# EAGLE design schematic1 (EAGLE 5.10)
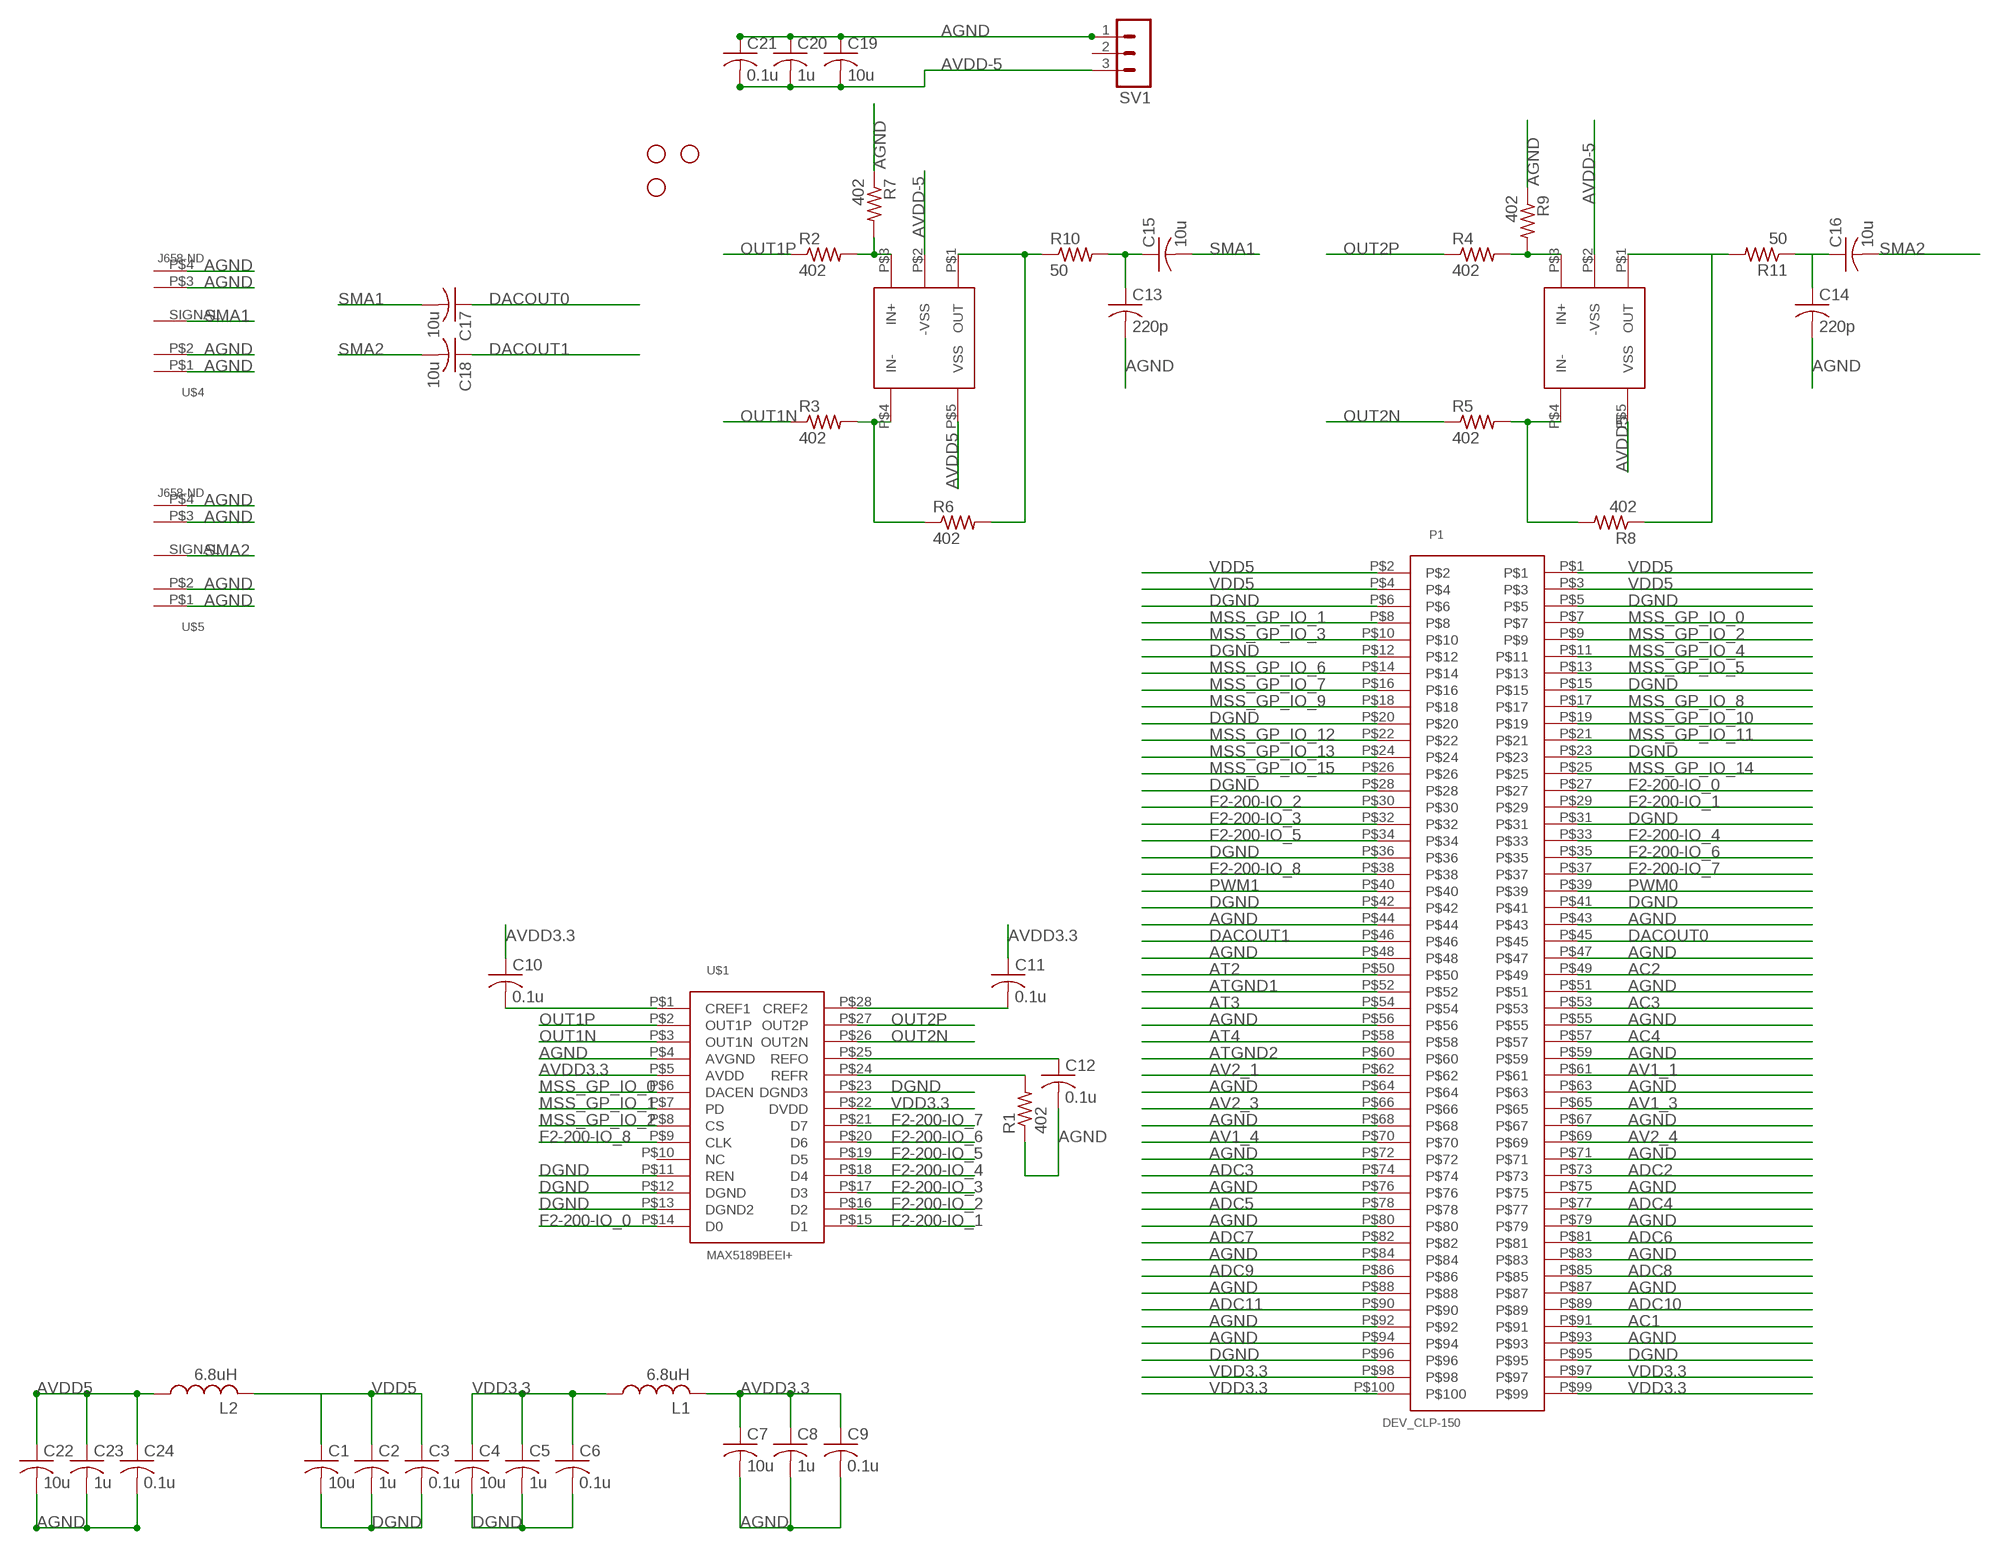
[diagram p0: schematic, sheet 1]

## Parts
C1  10u  C-USC0603  [C0603]
C2  1u  C-USC0603  [C0603]
C3  0.1u  C-USC0603  [C0603]
C4  10u  C-USC0603  [C0603]
C5  1u  C-USC0603  [C0603]
C6  0.1u  C-USC0603  [C0603]
C7  10u  C-USC0603  [C0603]
C8  1u  C-USC0603  [C0603]
C9  0.1u  C-USC0603  [C0603]
C10  0.1u  C-USC0603  [C0603]
C11  0.1u  C-USC0603  [C0603]
C12  0.1u  C-USC0603  [C0603]
C13  220p  C-USC0603  [C0603]
C14  220p  C-USC0603  [C0603]
C15  10u  C-USC0603  [C0603]
C16  10u  C-USC0603  [C0603]
C17  10u  C-USC0603  [C0603]
C18  10u  C-USC0603  [C0603]
C19  10u  C-USC0603  [C0603]
C20  1u  C-USC0603  [C0603]
C21  0.1u  C-USC0603  [C0603]
C22  10u  C-USC0603  [C0603]
C23  1u  C-USC0603  [C0603]
C24  0.1u  C-USC0603  [C0603]
JP1  STAND-OFF  [STAND-OFF]
JP2  STAND-OFF  [STAND-OFF]
JP3  STAND-OFF  [STAND-OFF]
L1  6.8uH  L-US  [L1210]
L2  6.8uH  L-US  [L1210]
P1  DEV_CLP-150  [CLP-150]
R1  402  R-US_R0603  [R0603]
R2  402  R-US_R0603  [R0603]
R3  402  R-US_R0603  [R0603]
R4  402  R-US_R0603  [R0603]
R5  402  R-US_R0603  [R0603]
R6  402  R-US_R0603  [R0603]
R7  402  R-US_R0603  [R0603]
R8  402  R-US_R0603  [R0603]
R9  402  R-US_R0603  [R0603]
R10  50  R-US_R0603  [R0603]
R11  50  R-US_R0603  [R0603]
SV1  MA03-1  [MA03-1]
U$1  MAX5189BEEI+  [QSOP]
U$3  MAX4104EUK+T  [SOT-5]
U$4  J658-ND  [SMA-SMD]
U$5  J658-ND  [SMA-SMD]
U$8  MAX4104EUK+T  [SOT-5]

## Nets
AC1: P1.P$91
AC2: P1.P$49
AC3: P1.P$53
AC4: P1.P$57
ADC2: P1.P$73
ADC3: P1.P$74
ADC4: P1.P$77
ADC5: P1.P$78
ADC6: P1.P$81
ADC7: P1.P$82
ADC8: P1.P$85
ADC9: P1.P$86
ADC10: P1.P$89
ADC11: P1.P$90
AGND: C7.2 C8.2 C9.2 C12.2 C13.2 C14.2 C19.1 C20.1 C21.1 C22.2 C23.2 C24.2 P1.P$43 P1.P$44 P1.P$47 P1.P$48 P1.P$51 P1.P$55 P1.P$56 P1.P$59 P1.P$63 P1.P$64 P1.P$67 P1.P$68 P1.P$71 P1.P$72 P1.P$75 P1.P$76 P1.P$79 P1.P$80 P1.P$83 P1.P$84 P1.P$87 P1.P$88 P1.P$92 P1.P$93 P1.P$94 R1.1 R7.1 R9.1 SV1.1 U$1.P$4(AVGND) U$4.P$1(GND1) U$4.P$2(GND2) U$4.P$3(GND3) U$4.P$4(GND4) U$5.P$1(GND1) U$5.P$2(GND2) U$5.P$3(GND3) U$5.P$4(GND4)
AT2: P1.P$50
AT3: P1.P$54
AT4: P1.P$58
ATGND1: P1.P$52
ATGND2: P1.P$60
AV1_1: P1.P$61
AV1_3: P1.P$65
AV1_4: P1.P$70
AV2_1: P1.P$62
AV2_3: P1.P$66
AV2_4: P1.P$69
AVDD3.3: C7.1 C8.1 C9.1 C10.1 C11.1 L1.2 U$1.P$5(AVDD)
AVDD5: C22.1 C23.1 C24.1 L2.1 U$3.P$5(VSS) U$8.P$5(VSS)
AVDD-5: C19.2 C20.2 C21.2 SV1.3 U$3.P$2(-VSS) U$8.P$2(-VSS)
DACOUT0: C17.1 P1.P$45
DACOUT1: C18.1 P1.P$46
DGND: C1.2 C2.2 C3.2 C4.2 C5.2 C6.2 P1.P$5 P1.P$6 P1.P$12 P1.P$15 P1.P$20 P1.P$23 P1.P$28 P1.P$31 P1.P$36 P1.P$41 P1.P$42 P1.P$95 P1.P$96 U$1.P$11(REN) U$1.P$12(DGND) U$1.P$13(DGND2) U$1.P$23(DGND3)
F2-200-IO_0: P1.P$27 U$1.P$14(D0)
F2-200-IO_1: P1.P$29 U$1.P$15(D1)
F2-200-IO_2: P1.P$30 U$1.P$16(D2)
F2-200-IO_3: P1.P$32 U$1.P$17(D3)
F2-200-IO_4: P1.P$33 U$1.P$18(D4)
F2-200-IO_5: P1.P$34 U$1.P$19(D5)
F2-200-IO_6: P1.P$35 U$1.P$20(D6)
F2-200-IO_7: P1.P$37 U$1.P$21(D7)
F2-200-IO_8: P1.P$38 U$1.P$9(CLK)
MSS_GP_IO_0: P1.P$7 U$1.P$6(DACEN)
MSS_GP_IO_1: P1.P$8 U$1.P$7(PD)
MSS_GP_IO_2: P1.P$9 U$1.P$8(CS)
MSS_GP_IO_3: P1.P$10
MSS_GP_IO_4: P1.P$11
MSS_GP_IO_5: P1.P$13
MSS_GP_IO_6: P1.P$14
MSS_GP_IO_7: P1.P$16
MSS_GP_IO_8: P1.P$17
MSS_GP_IO_9: P1.P$18
MSS_GP_IO_10: P1.P$19
MSS_GP_IO_11: P1.P$21
MSS_GP_IO_12: P1.P$22
MSS_GP_IO_13: P1.P$24
MSS_GP_IO_14: P1.P$25
MSS_GP_IO_15: P1.P$26
N$1: R5.2 R8.2 U$8.P$4(IN-)
N$2: R4.2 R9.2 U$8.P$3(IN+)
N$3: R6.2 R10.1 U$3.P$1(OUT)
N$4: R3.2 R6.1 U$3.P$4(IN-)
N$5: C10.2 U$1.P$1(CREF1)
N$6: C13.1 C15.1 R10.2
N$7: R2.2 R7.2 U$3.P$3(IN+)
N$8: R8.1 R11.2 U$8.P$1(OUT)
N$9: C14.1 C16.1 R11.1
N$23: R1.2 U$1.P$24(REFR)
N$24: C12.1 U$1.P$25(REFO)
N$27: C11.2 U$1.P$28(CREF2)
OUT1N: R3.1 U$1.P$3(OUT1N)
OUT1P: R2.1 U$1.P$2(OUT1P)
OUT2N: R5.1 U$1.P$26(OUT2N)
OUT2P: R4.1 U$1.P$27(OUT2P)
PWM0: P1.P$39
PWM1: P1.P$40
SMA1: C15.2 C17.2 U$4.SIGNAL
SMA2: C16.2 C18.2 U$5.SIGNAL
VDD3.3: C4.1 C5.1 C6.1 L1.1 P1.P$97 P1.P$98 P1.P$99 P1.P$100 U$1.P$22(DVDD)
VDD5: C1.1 C2.1 C3.1 L2.2 P1.P$1 P1.P$2 P1.P$3 P1.P$4
Unconnected: SV1.2 U$1.P$10(NC)

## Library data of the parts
C1-C24 = rcl:C-US: CAPACITOR, American symbol
JP1-JP3 = SparkFun:STAND-OFF: Stand Off
L1 L2 = sam:L-US: INDUCTOR, American symbol
P1 = EECS370:DEV_CLP-150
R1-R11 = rcl:R-US_: RESISTOR, American symbol
SV1 = con-lstb:MA03-1: PIN HEADER; OC_FARNELL: unknown; OC_NEWARK: unknown
U$1 = sam:MAX5189BEEI+
U$3 U$8 = sam:MAX4104EUK+T
U$4 U$5 = sam:J658-ND

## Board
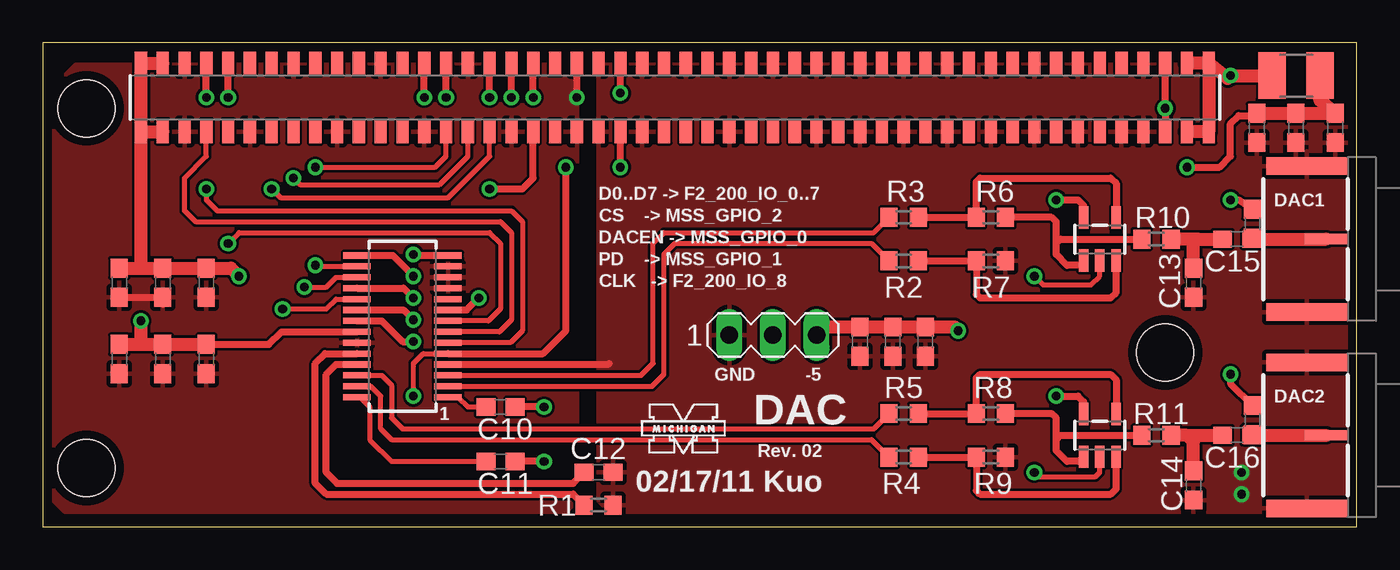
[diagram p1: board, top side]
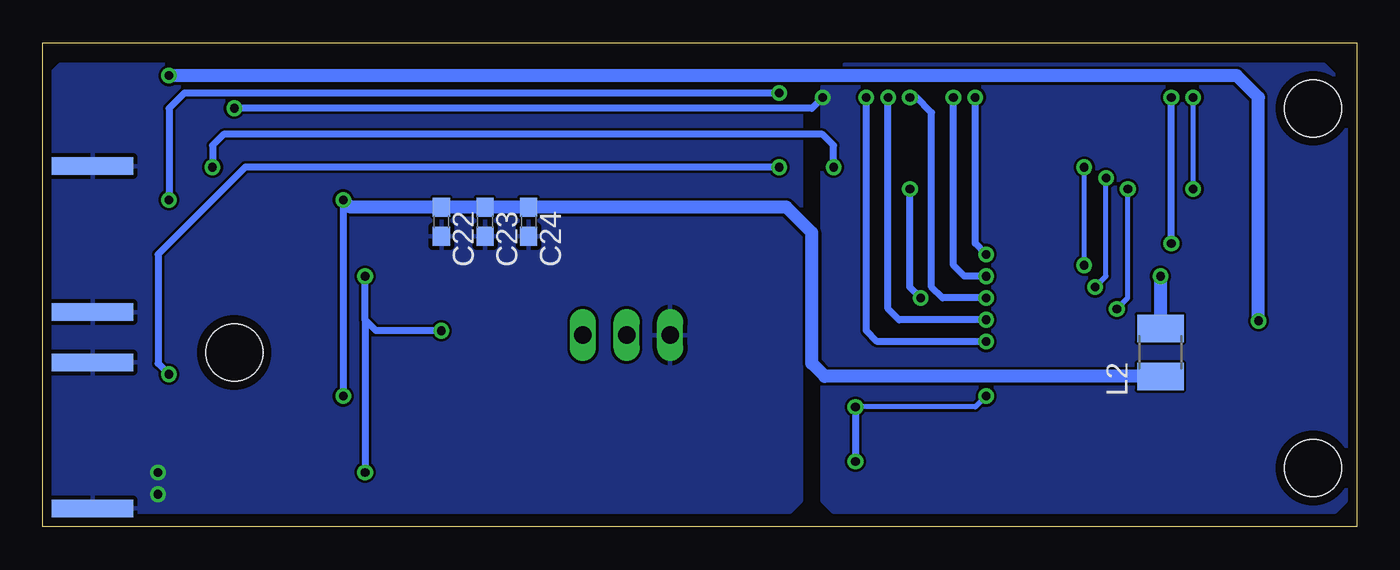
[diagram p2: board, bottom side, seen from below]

Size 76.56 x 28.19 mm. Coordinates in mm from the lower left corner, seen from the top.
Outline: 0,0 76.56,0 76.56,28.19 0,28.19 0,0
Copper layers (1*16): Top 0.0178mm / dielectric 1.4986mm / Bottom 0.0178mm
Design rules "SSC-EAGLE-2Lyr_v1.0.0.3": minimum track width 6mil, minimum drill 14mil, track to track 6mil, track to pad 6mil, pad to pad 6mil, via to via 6mil, smd to smd 6mil, copper to edge 20mil, drill to drill 16mil, minimum pad ring 8mil, minimum via ring 8mil, stop-mask expansion 3mil, vias tented up to drill 0mil, thermal gap 10mil

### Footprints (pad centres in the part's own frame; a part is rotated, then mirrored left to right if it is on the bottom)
C0603 = smd 1.1 x 1: 1 -0.85,0; 2 0.85,0
STAND-OFF = hole 3.302: 0,0
L1210 = smd 1.6 x 2.7: 1 -1.4,0; 2 1.4,0
CLP-150 = smd 0.711 x 1.35: P$1 -31.115,1.99; P$2 -31.115,-1.99; P$3 -29.845,1.99; P$4 -29.845,-1.99; P$5 -28.575,1.99; P$6 -28.575,-1.99; P$7 -27.305,1.99; P$8 -27.305,-1.99; P$9 -26.035,1.99; P$10 -26.035,-1.99; P$11 -24.765,1.99; P$12 -24.765,-1.99; P$13 -23.495,1.99; P$14 -23.495,-1.99; P$15 -22.225,1.99; P$16 -22.225,-1.99; P$17 -20.955,1.99; P$18 -20.955,-1.99; P$19 -19.685,1.99; P$20 -19.685,-1.99; P$21 -18.415,1.99; P$22 -18.415,-1.99; P$23 -17.145,1.99; P$24 -17.145,-1.99; P$25 -15.875,1.99; P$26 -15.875,-1.99; P$27 -14.605,1.99; P$28 -14.605,-1.99; P$29 -13.335,1.99; P$30 -13.335,-1.99; P$31 -12.065,1.99; P$32 -12.065,-1.99; P$33 -10.795,1.99; P$34 -10.795,-1.99; P$35 -9.525,1.99; P$36 -9.525,-1.99; P$37 -8.255,1.99; P$38 -8.255,-1.99; P$39 -6.985,1.99; P$40 -6.985,-1.99; P$41 -5.715,1.99; P$42 -5.715,-1.99; P$43 -4.445,1.99; P$44 -4.445,-1.99; P$45 -3.175,1.99; P$46 -3.175,-1.99; P$47 -1.905,1.99; P$48 -1.905,-1.99; P$49 -0.635,1.99; P$50 -0.635,-1.99; P$51 0.635,1.99; P$52 0.635,-1.99; P$53 1.905,1.99; P$54 1.905,-1.99; P$55 3.175,1.99; P$56 3.175,-1.99; P$57 4.445,1.99; P$58 4.445,-1.99; P$59 5.715,1.99; P$60 5.715,-1.99; P$61 6.985,1.99; P$62 6.985,-1.99; P$63 8.255,1.99; P$64 8.255,-1.99; P$65 9.525,1.99; P$66 9.525,-1.99; P$67 10.795,1.99; P$68 10.795,-1.99; P$69 12.065,1.99; P$70 12.065,-1.99; P$71 13.335,1.99; P$72 13.335,-1.99; P$73 14.605,1.99; P$74 14.605,-1.99; P$75 15.875,1.99; P$76 15.875,-1.99; P$77 17.145,1.99; P$78 17.145,-1.99; P$79 18.415,1.99; P$80 18.415,-1.99; P$81 19.685,1.99; P$82 19.685,-1.99; P$83 20.955,1.99; P$84 20.955,-1.99; P$85 22.225,1.99; P$86 22.225,-1.99; P$87 23.495,1.99; P$88 23.495,-1.99; P$89 24.765,1.99; P$90 24.765,-1.99; P$91 26.035,1.99; P$92 26.035,-1.99; P$93 27.305,1.99; P$94 27.305,-1.99; P$95 28.575,1.99; P$96 28.575,-1.99; P$97 29.845,1.99; P$98 29.845,-1.99; P$99 31.115,1.99; P$100 31.115,-1.99
R0603 = smd 1 x 1.1: 1 -0.85,0; 2 0.85,0
MA03-1 = drill 1.016 long: 1 -2.54,0; 2 0,0; 3 2.54,0
QSOP = smd 1.6 x 0.356: P$1 -2.655,4.128; P$2 -2.655,3.493; P$3 -2.655,2.857; P$4 -2.655,2.223; P$5 -2.655,1.587; P$6 -2.655,0.953; P$7 -2.655,0.318; P$8 -2.655,-0.318; P$9 -2.655,-0.953; P$10 -2.655,-1.587; P$11 -2.655,-2.223; P$12 -2.655,-2.857; P$13 -2.655,-3.493; P$14 -2.655,-4.128; P$15 2.655,-4.128; P$16 2.655,-3.493; P$17 2.655,-2.857; P$18 2.655,-2.223; P$19 2.655,-1.587; P$20 2.655,-0.953; P$21 2.655,-0.318; P$22 2.655,0.318; P$23 2.655,0.953; P$24 2.655,1.587; P$25 2.655,2.223; P$26 2.655,2.857; P$27 2.655,3.493; P$28 2.655,4.128
SOT-5 = smd 1.3 x 0.55: P$1 -1.25,0.95; P$2 -1.25,0; P$3 -1.25,-0.95; P$4 1.25,-0.95; P$5 1.25,0.95
SMA-SMD = smd 1.02 x 4.75: P$1 -4.25,0; P$2 4.25,0 | smd 1.02 x 4.75 bottom: P$3 4.25,0; P$4 -4.25,0 | smd 0.6 x 2.5: SIGNAL 0,1.125

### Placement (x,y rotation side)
C1  4.45,14.22 270 top
C2  9.53,14.22 270 top
C3  6.99,14.22 270 top
C4  6.99,9.78 270 top
C5  9.53,9.78 270 top
C6  4.45,9.78 270 top
C7  75.31,23.24 270 top
C8  73.03,23.24 270 top
C9  70.74,23.24 270 top
C10  26.67,6.99 180 top
C11  26.67,3.81 180 top
C12  32.38,3.17 0 top
C13  67.06,14.22 270 top
C14  67.06,2.41 270 top
C15  69.6,16.76 0 top
C16  69.6,5.33 0 top
C17  70.48,17.65 270 top
C18  70.48,6.22 270 top
C19  47.62,10.79 90 top
C20  49.53,10.79 90 top
C21  51.44,10.79 90 top
C22  53.34,17.78 270 bottom
C23  50.8,17.78 270 bottom
C24  48.26,17.78 270 bottom
JP1  2.54,3.43 0 top
JP2  2.54,24.38 0 top
JP3  65.41,10.16 0 top
L1  73.03,26.29 0 top
L2  11.43,10.16 90 bottom
P1  36.83,25.02 0 top
R1  32.38,1.27 180 top
R2  50.16,15.49 0 top
R3  50.16,18.03 0 top
R4  50.16,4.06 0 top
R5  50.16,6.6 0 top
R6  55.24,18.03 0 top
R7  55.24,15.49 180 top
R8  55.24,6.6 180 top
R9  55.24,4.06 180 top
R10  64.9,16.76 0 top
R11  64.9,5.33 180 top
SV1  42.55,11.18 0 top
U$1  20.95,11.68 180 top
U$3  61.59,16.76 90 top
U$4  73.66,16.76 270 top
U$5  73.66,5.33 270 top
U$6  [UMICH]  34.8,4.06 0 top
U$8  61.59,5.33 90 top

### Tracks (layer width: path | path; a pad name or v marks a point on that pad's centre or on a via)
AGND  (via drill 0.51)
  Top 0.406: U$1.P$4 32.96,9.46 33.02,9.53
  other vias: 69.85,3.17 69.85,1.91
  pour Top: 76.2,26.29 76.2,1.52 75.56,0.89 33.02,0.89 32.38,1.52 32.38,26.92 75.56,26.92
  pour Bottom: 76.2,26.29 75.56,26.92 32.38,26.92 32.38,1.52 33.02,0.89 75.56,0.89 76.2,1.52
AVDD3.3  (via drill 0.51)
  Top 0.305: U$1.P$5 22.16,10.1 21.59,9.53 v21.59,7.62
  Top 0.406: v66.67,20.95 68.58,20.95 69.22,21.59 69.22,23.5 69.68,23.96 70.61,23.96 C9.1 | v29.21,3.81 C11.1 | v29.21,6.99 C10.1 | v30.48,20.95 30.48,11.43 29.15,10.1 U$1.P$5
  Top 0.762: L1.2 74.42,24.85 C7.1 C8.1 C9.1
  Bottom 0.305: v21.59,7.62 22.23,6.99 v29.21,6.99
  Bottom 0.406: v66.67,20.95 66.67,22.23 66.04,22.86 31.11,22.86 30.48,22.23 v30.48,20.95 | v29.21,6.99 v29.21,3.81
AVDD5  (via drill 0.51)
  Top 0.406: U$8.P$5 60.65,7.3 60.33,7.62 v59.05,7.62 | U$3.P$5 60.65,18.73 60.33,19.05 v59.05,19.05
  Bottom 0.406: v59.05,19.05 v59.05,7.62
  Bottom 0.762: L2.1 30.98,8.76 31.75,9.53 31.75,17.14 33.23,18.63 C24.1 C23.1 C22.1 58.63,18.63 v59.05,19.05
AVDD-5  (via drill 0.51)
  Top 0.305: U$8.P$2 61.59,3.17 61.34,2.92 58.04,2.92 v57.78,3.17 | U$3.P$2 61.59,14.61 61.09,14.1 58.29,14.1 v57.78,14.61
  Top 0.762: SV1.3 45.55,11.64 C19.2 C20.2 C21.2 53.12,11.64 v53.34,11.43
  Bottom 0.406: 57.78,12.06 v57.78,14.61 | v53.34,11.43 57.15,11.43 57.78,12.06 | 57.78,12.06 v57.78,3.17
DACOUT0  (via drill 0.51)
  Top 0.406: v33.66,25.27 P1.P$45 | v69.22,19.05 69.68,19.05 C17.1
  Bottom 0.406: v33.66,25.27 68.33,25.27 69.22,24.38 v69.22,19.05
DACOUT1  (via drill 0.51)
  Top 0.406: v33.66,20.95 P1.P$46 | v69.22,8.89 69.22,8.34 C18.1
  Bottom 0.406: v33.66,20.95 64.77,20.95 69.85,15.88 69.85,9.53 v69.22,8.89
DGND  (via drill 0.51)
  Top 0.406: C1.2 C3.2 6.99,12.95 | v31.11,25.02 P1.P$41 | P1.P$96 v65.41,24.38 P1.P$95
  Bottom 0.406: v65.41,24.38 31.75,24.38 v31.11,25.02
  pour Top: 0.64,25.65 0.64,1.52 1.27,0.89 30.48,0.89 31.11,1.52 31.11,25.65 29.84,26.92 1.91,26.92
  pour Bottom: 0.64,25.65 0.64,1.52 1.27,0.89 30.48,0.89 31.11,1.52 31.11,25.65 29.84,26.92 1.91,26.92
F2-200-IO_0  (via drill 0.51)
  Top 0.406: v22.23,25.02 P1.P$27 | U$1.P$14 21.65,15.81 v21.59,15.88
  Bottom 0.406: v22.23,25.02 22.23,16.51 v21.59,15.88
F2-200-IO_1  (via drill 0.51)
  Top 0.406: v23.5,25.02 P1.P$29 | U$1.P$15 20.38,15.81 v21.59,14.61
  Bottom 0.406: v23.5,25.02 23.5,15.24 22.86,14.61 v21.59,14.61
F2-200-IO_2  (via drill 0.51)
  Top 0.305: P1.P$30 23.5,21.59 22.86,20.95 v15.88,20.95 | U$1.P$16 15.94,15.18 v15.88,15.24
  Bottom 0.305: v15.88,15.24 v15.88,20.95
F2-200-IO_3  (via drill 0.51)
  Top 0.305: P1.P$32 24.77,21.59 23.11,19.94 14.99,19.94 v14.61,20.32 | U$1.P$17 17.08,14.54 16.51,13.97 v15.24,13.97
  Bottom 0.305: v14.61,20.32 14.61,14.61 v15.24,13.97
F2-200-IO_4  (via drill 0.51)
  Top 0.406: v26.04,25.02 P1.P$33 | U$1.P$18 21.02,13.91 v21.59,13.34
  Bottom 0.406: v21.59,13.34 24.13,13.34 24.77,13.97 24.77,24.13 25.65,25.02 v26.04,25.02
F2-200-IO_5  (via drill 0.51)
  Top 0.305: P1.P$34 26.04,21.59 23.62,19.18 13.84,19.18 v13.34,19.68 | U$1.P$19 17.08,13.27 16.51,12.7 v13.97,12.7
  Bottom 0.305: v13.34,19.68 13.34,13.34 v13.97,12.7
F2-200-IO_6  (via drill 0.51)
  Top 0.406: v27.3,25.02 P1.P$35 | U$1.P$20 21.02,12.64 v21.59,12.06
  Bottom 0.406: v27.3,25.02 27.3,12.7 26.67,12.06 v21.59,12.06
F2-200-IO_7  (via drill 0.51)
  Top 0.406: v28.57,25.02 P1.P$37 | U$1.P$21 19.75,12 20.95,10.79 v21.59,10.79
  Bottom 0.406: v28.57,25.02 28.57,11.43 27.94,10.79 v21.59,10.79
F2-200-IO_8  (via drill 0.51)
  Top 0.406: U$1.P$9 24.7,12.64 v25.4,13.34 | v26.04,19.68 27.94,19.68 28.57,20.32 P1.P$38
  Bottom 0.406: v25.4,13.34 26.04,13.97 v26.04,19.68
MSS_GP_IO_0  (via drill 0.51)
  Top 0.305: U$1.P$6 27.24,10.73 27.94,11.43 27.94,17.78 27.3,18.41 10.16,18.41 9.53,19.05 v9.53,19.68
  Top 0.406: v9.53,25.02 P1.P$7
  Bottom 0.305: v9.53,19.68 v9.53,25.02
MSS_GP_IO_1
  Top 0.305: U$1.P$7 26.61,11.37 27.3,12.06 27.3,17.14 26.67,17.78 8.89,17.78 8.26,18.41 8.26,20.32 9.53,21.59 P1.P$8
MSS_GP_IO_2  (via drill 0.51)
  Top 0.305: U$1.P$8 25.97,12 26.67,12.7 26.67,16.51 26.04,17.14 11.43,17.14 v10.79,16.51
  Top 0.406: v10.79,25.02 P1.P$9
  Bottom 0.406: v10.79,16.51 v10.79,25.02
N$1
  Top 0.406: R5.2 R8.2 54.4,8.68 54.61,8.89 62.23,8.89 62.55,8.57 U$8.P$4
N$2
  Top 0.406: R4.2 R9.2 54.4,2.12 54.61,1.91 62.23,1.91 62.55,2.22 U$8.P$3
N$3
  Top 0.406: 59.05,16.51 59.05,15.88 59.69,15.24 60.62,15.24 U$3.P$1 | R10.1 59.31,16.76 59.05,16.51 | R6.2 58.8,18.03 59.05,17.78 59.05,16.51
N$4
  Top 0.406: U$3.P$4 62.55,20 62.23,20.32 54.61,20.32 54.4,20.11 R6.1 R3.2
N$5
  Top 0.305: U$1.P$1 24.19,7.56 24.77,6.99 C10.2
N$6
  Top 0.762: 67.31,16.76 R10.2 | 67.31,16.76 C15.1 | C13.1 67.06,16.51 67.31,16.76
N$7
  Top 0.406: R2.2 R7.2 54.4,13.55 54.61,13.34 62.23,13.34 62.55,13.65 U$3.P$3
N$8
  Top 0.406: R8.1 58.8,6.6 59.05,6.35 59.05,5.08 | 59.05,5.08 59.05,4.45 59.69,3.81 60.37,3.81 U$8.P$1 | R11.2 59.31,5.33 59.05,5.08
N$9
  Top 0.762: 66.67,5.33 R11.1 | 66.67,5.33 C16.1 | C14.1 67.06,4.95 66.67,5.33
N$23
  Top 0.406: U$1.P$24 16.45,10.1 15.88,9.53 15.88,2.54 16.51,1.91 30.9,1.91 R1.2
N$24
  Top 0.406: U$1.P$25 17.08,9.46 16.51,8.89 16.51,3.17 17.14,2.54 30.9,2.54 C12.1
N$27
  Top 0.305: U$1.P$28 18.48,7.56 19.05,6.99 19.05,5.08 20.32,3.81 C11.2
OUT1N
  Top 0.305: U$1.P$3 34.86,8.83 35.56,9.53 35.56,16.51 36.2,17.14 48.43,17.14 R3.1
OUT1P
  Top 0.305: U$1.P$2 35.5,8.19 36.2,8.89 36.2,15.88 36.83,16.51 48.3,16.51 R2.1
OUT2N
  Top 0.305: U$1.P$26 19.75,8.83 20.32,8.26 20.32,6.35 20.95,5.71 48.43,5.71 R5.1
OUT2P
  Top 0.305: U$1.P$27 19.11,8.19 19.68,7.62 19.68,5.71 20.32,5.08 48.3,5.08 R4.1
SMA1
  Top 0.762: C15.2 C17.2 70.52,16.76 U$4.SIGNAL
SMA2
  Top 0.762: U$5.SIGNAL 70.52,5.33 C18.2 C16.2
VDD3.3  (via drill 0.51)
  Top 0.406: U$1.P$22 13.91,11.37 13.17,10.63 C5.1
  Top 0.762: P1.P$99 P1.P$100 P1.P$98 | P1.P$99 P1.P$97 | P1.P$99 69.05,26.12 v69.22,26.29 L1.1 | C6.1 5.71,10.63 | 5.71,10.63 C4.1 C5.1 | 5.71,10.63 v5.71,12
  Bottom 0.762: v69.22,26.29 6.99,26.29 5.71,25.02 v5.71,12
VDD5  (via drill 0.51)
  Top 0.762: P1.P$2 P1.P$4 | C1.1 5.71,15.07 | 5.71,15.07 C3.1 C2.1 10.96,15.07 v11.43,14.61 | P1.P$2 P1.P$1 P1.P$3 | 5.71,15.07 P1.P$2
  Bottom 0.762: v11.43,14.61 L2.2

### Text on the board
tPlace: D0..D7 -> F2_200_IO_0..7 | DAC1 | CS -> MSS_GPIO_2 | DACEN -> MSS_GPIO_0 | PD -> MSS_GPIO_1 | CLK -> F2_200_IO_8 | GND | -5 | DAC2 | 1 | DAC | Rev. 02 | 02/17/11 Kuo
